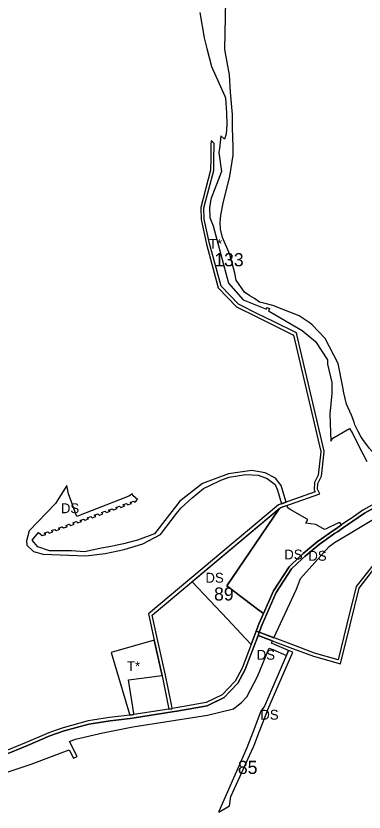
# Model space of a CAD drawing. Extents: x -477304 to -465641, y -1159113 to -1149285.
# Drawn here: x -470101 to -469785, y -1153834 to -1153108 of the extents above; entities that cross this region are included whole.
import ezdxf

# ---------------------------------------------------------------- set-up
doc = ezdxf.new("R2010")
doc.units = 0
for name, color, linetype in [('14', 7, 'Continuous'), ('17', 7, 'Continuous'), ('35', 7, 'Continuous'), ('4', 7, 'Continuous'), ('60', 7, 'Continuous')]:
    doc.layers.add(name, color=color, linetype=linetype)

msp = doc.modelspace()

# ---------------------------------------------------------------- linework, layer by layer
at = {"layer": '14'}
for p, q in [((-469861.91, -1153557.27), (-469941.15, -1153623.82)), ((-469941.15, -1153623.82), (-469908.95, -1153658.04)), ((-469885.46, -1153645.71), (-469895.39, -1153638.21)), ((-469881.57, -1153648.65), (-469885.46, -1153645.71)), ((-469876.12, -1153652.76), (-469881.57, -1153648.65)), ((-469908.95, -1153658.04), (-469892.51, -1153675.5)), ((-469887.31, -1153681.03), (-469882.68, -1153668.8)), ((-469892.51, -1153675.5), (-469887.31, -1153681.03)), ((-469853.16, -1153686.42), (-469875.1, -1153737.35)), ((-469849.49, -1153688.02), (-469853.16, -1153686.42)), ((-469875.1, -1153737.35), (-469878.47, -1153741.63)), ((-469878.47, -1153741.63), (-469885.5, -1153760.21)), ((-469879.65, -1153759.93), (-469872.26, -1153740.43)), ((-469888.77, -1153782.27), (-469885.17, -1153774.35)), ((-469897.31, -1153801.05), (-469888.77, -1153782.27)), ((-469899.91, -1153795.18), (-469916.58, -1153833.33)), ((-469905.73, -1153819.57), (-469897.31, -1153801.05)), ((-469907.11, -1153828.02), (-469905.73, -1153819.57)), ((-469916.76, -1153833.74), (-469907.11, -1153828.02)), ((-469916.58, -1153833.33), (-469916.76, -1153833.74))]:
    msp.add_line(p, q, dxfattribs=at)
for points in [[(-469895.39, -1153638.21), (-469909.36, -1153627.65), (-469861.91, -1153557.27)], [(-469882.68, -1153668.8), (-469879.93, -1153661.52), (-469876.12, -1153652.76)], [(-469872.26, -1153740.43), (-469872.18, -1153740.2), (-469849.49, -1153688.02)], [(-469885.5, -1153760.21), (-469891.17, -1153775.19), (-469899.91, -1153795.18)], [(-469885.17, -1153774.35), (-469884.84, -1153773.63), (-469879.65, -1153759.93)]]:
    msp.add_lwpolyline(points, dxfattribs=at)
at = {"layer": '17'}
for p, q in [((-469975.46, -1153677.14), (-470014.7, -1153688.4)), ((-469968.4, -1153709.21), (-469975.46, -1153677.14)), ((-470014.7, -1153688.4), (-469998.01, -1153744.48)), ((-469998.82, -1153713.09), (-469968.4, -1153709.21)), ((-469994.18, -1153743.75), (-469998.82, -1153713.09)), ((-469998.01, -1153744.48), (-469997.87, -1153745.36)), ((-469997.87, -1153745.36), (-469994.02, -1153744.79)), ((-469994.02, -1153744.79), (-469994.18, -1153743.75))]:
    msp.add_line(p, q, dxfattribs=at)
at = {"layer": '35'}
for p, q in [((-469934.01, -1153105.13), (-469930.18, -1153128.18)), ((-469930.18, -1153128.18), (-469927.69, -1153137.79)), ((-469927.69, -1153137.79), (-469923.48, -1153154.05)), ((-469923.48, -1153154.05), (-469911.32, -1153181.38)), ((-469911.32, -1153181.38), (-469910.63, -1153182.94)), ((-469910.63, -1153182.94), (-469909.76, -1153196.47)), ((-469909.76, -1153196.47), (-469909.59, -1153207.08)), ((-469909.59, -1153207.08), (-469909.92, -1153215.75)), ((-469909.92, -1153215.75), (-469910.65, -1153217.65)), ((-469903.69, -1153227.03), (-469904.29, -1153210.3)), ((-469914.79, -1153217.53), (-469916.18, -1153229.08)), ((-469911.46, -1153220.44), (-469914.79, -1153217.53)), ((-469916.18, -1153229.08), (-469916.62, -1153232.73)), ((-469903.7, -1153232.71), (-469903.69, -1153227.03)), ((-469903.79, -1153235.09), (-469903.7, -1153232.71)), ((-469915.62, -1153296.43), (-469914.87, -1153289.68)), ((-469915.06, -1153302.48), (-469915.62, -1153296.43)), ((-469921.92, -1153299.34), (-469907.91, -1153351.56)), ((-469913.29, -1153310.07), (-469915.06, -1153302.48)), ((-469907.91, -1153351.56), (-469894.62, -1153366.93)), ((-469884.19, -1153365.79), (-469888.57, -1153363.17)), ((-469879.81, -1153368.87), (-469884.19, -1153365.79)), ((-469875.85, -1153369.85), (-469879.81, -1153368.87)), ((-469872.98, -1153373.93), (-469870.68, -1153374.87)), ((-469870.68, -1153374.87), (-469871.54, -1153376.88)), ((-469833.46, -1153388.17), (-469843.6, -1153381.6)), ((-469831.79, -1153389.68), (-469833.46, -1153388.17)), ((-469819.99, -1153402.16), (-469831.79, -1153389.68)), ((-469817.76, -1153421.41), (-469817.94, -1153425.43)), ((-469817.94, -1153425.43), (-469813.92, -1153442.22)), ((-469813.92, -1153442.22), (-469813.78, -1153452.18)), ((-469796.05, -1153472.06), (-469800.64, -1153461.93)), ((-469793.44, -1153478.47), (-469796.05, -1153472.06)), ((-469792.99, -1153480.68), (-469793.44, -1153478.47)), ((-469789.85, -1153486.93), (-469792.99, -1153480.68)), ((-469787.54, -1153491.35), (-469789.85, -1153486.93)), ((-469785.57, -1153494.24), (-469787.54, -1153491.35)), ((-469814.76, -1153495.63), (-469812.93, -1153492.98)), ((-469789.27, -1153500.37), (-469781.93, -1153514.31)), ((-469892.13, -1153526.17), (-469880.96, -1153526.58)), ((-470055.02, -1153536.1), (-470065.3, -1153552.42)), ((-470053.46, -1153543.75), (-470055.02, -1153536.1)), ((-469931.48, -1153534.12), (-469952.3, -1153550.45)), ((-469925.02, -1153536.07), (-469915.04, -1153531.24)), ((-469859.91, -1153535.97), (-469865.11, -1153529.32)), ((-470050.53, -1153551.96), (-470053.46, -1153543.75)), ((-469990.92, -1153548.94), (-469994.76, -1153545.62)), ((-469951.31, -1153556.6), (-469940.9, -1153547.21)), ((-470065.3, -1153552.42), (-470089.45, -1153577.34)), ((-470048.31, -1153558.05), (-470050.53, -1153551.96)), ((-470010.53, -1153556.09), (-470007.27, -1153554.92)), ((-470009.21, -1153557.2), (-470010.53, -1153556.09)), ((-469996.18, -1153552.52), (-469997.5, -1153551.43)), ((-469955.18, -1153561.55), (-469951.31, -1153556.6)), ((-469860.9, -1153556.42), (-469861.91, -1153557.27)), ((-469854.62, -1153554.21), (-469860.9, -1153556.42)), ((-469859.56, -1153552.77), (-469855.45, -1153551.32)), ((-469853.93, -1153556.57), (-469854.62, -1153554.21)), ((-469851.67, -1153557.88), (-469853.93, -1153556.57)), ((-469836.17, -1153566.88), (-469851.67, -1153557.88)), ((-470046.08, -1153564.42), (-470048.31, -1153558.05)), ((-470033.34, -1153564.33), (-470032.01, -1153565.41)), ((-470030.11, -1153563.14), (-470026.82, -1153561.98)), ((-470026.82, -1153561.98), (-470025.48, -1153563.09)), ((-469969.79, -1153580.6), (-469955.18, -1153561.55)), ((-470051.56, -1153572.43), (-470048.28, -1153571.25)), ((-470045.03, -1153570.11), (-470041.76, -1153568.94)), ((-469804.99, -1153571.96), (-469806.61, -1153569.92)), ((-470089.45, -1153577.34), (-470091.71, -1153586.53)), ((-470072.38, -1153578.4), (-470071.08, -1153579.47)), ((-470054.82, -1153573.62), (-470056.14, -1153572.54)), ((-469819.05, -1153575.7), (-469820.5, -1153576.22)), ((-470091.71, -1153586.53), (-470091.43, -1153590.56)), ((-469990.88, -1153585.8), (-470003.56, -1153589.31)), ((-469986, -1153589.39), (-469969.79, -1153580.6)), ((-469811.4, -1153588.14), (-469804.73, -1153584.11)), ((-470025.19, -1153593.64), (-470038.9, -1153596.57)), ((-470003.06, -1153594.4), (-469986, -1153589.39)), ((-469845.92, -1153630.44), (-469842.45, -1153620.83)), ((-469866.58, -1153674.9), (-469845.92, -1153630.44)), ((-469895.39, -1153638.21), (-469885.46, -1153645.71)), ((-469885.46, -1153645.71), (-469881.57, -1153648.65)), ((-469881.57, -1153648.65), (-469876.12, -1153652.76)), ((-469880.94, -1153672.67), (-469890.22, -1153697.21)), ((-469880.13, -1153672.98), (-469880.94, -1153672.67)), ((-469871.3, -1153676.32), (-469880.13, -1153672.98)), ((-469879.88, -1153669.86), (-469866.58, -1153674.9)), ((-469867.85, -1153677.63), (-469871.3, -1153676.32)), ((-469868.8, -1153679.68), (-469867.85, -1153677.63)), ((-469865.9, -1153680.93), (-469868.8, -1153679.68)), ((-469853.16, -1153686.42), (-469865.9, -1153680.93)), ((-469881.47, -1153710.08), (-469871.25, -1153684.94)), ((-469871.25, -1153684.94), (-469870.91, -1153684.21)), ((-469870.91, -1153684.21), (-469867.51, -1153685.68)), ((-469867.51, -1153685.68), (-469855.14, -1153691.01)), ((-469855.14, -1153691.01), (-469853.16, -1153686.42)), ((-469892.8, -1153703.93), (-469899.47, -1153716.14)), ((-469891.26, -1153728.85), (-469881.47, -1153710.08)), ((-469896.16, -1153733.92), (-469891.26, -1153728.85)), ((-469903.47, -1153739.49), (-469896.16, -1153733.92)), ((-469995.09, -1153756.04), (-469927.03, -1153745.53)), ((-469927.03, -1153745.53), (-469903.47, -1153739.49)), ((-470010.4, -1153749.91), (-470015.72, -1153750.56)), ((-470022.46, -1153761.65), (-469995.09, -1153756.04)), ((-470045.67, -1153783.06), (-470052.8, -1153769.37)), ((-470087.67, -1153789.98), (-470052.84, -1153777.05)), ((-470052.84, -1153777.05), (-470048.96, -1153784.66)), ((-470048.96, -1153784.66), (-470045.67, -1153783.06))]:
    msp.add_line(p, q, dxfattribs=at)
for points in [[(-469906.22, -1153177.73), (-469906.93, -1153161.67), (-469911.29, -1153138.57), (-469910.39, -1153094.13), (-469908.46, -1153082.97)], [(-469904.29, -1153210.3), (-469904.3, -1153198.04), (-469906.22, -1153177.73)], [(-469910.65, -1153217.65), (-469911.03, -1153218.63), (-469911.46, -1153220.44)], [(-469916.62, -1153232.73), (-469914.2, -1153249.76), (-469924.01, -1153275.25), (-469925.36, -1153283.09)], [(-469914.87, -1153289.68), (-469912.78, -1153278.79), (-469906.72, -1153254.26), (-469903.79, -1153235.09)], [(-469925.36, -1153283.09), (-469925.04, -1153291.71), (-469921.92, -1153299.34)], [(-469902.03, -1153342.48), (-469906.82, -1153325.51), (-469913.29, -1153310.07)], [(-469888.57, -1153363.17), (-469893.22, -1153359.8), (-469901.02, -1153348.86), (-469902.03, -1153342.48)], [(-469894.62, -1153366.93), (-469873.41, -1153375.37), (-469872.98, -1153373.93)], [(-469843.6, -1153381.6), (-469867.5, -1153371.92), (-469875.85, -1153369.85)], [(-469871.54, -1153376.88), (-469840.78, -1153394.87), (-469828.75, -1153404.82), (-469817.76, -1153421.41)], [(-469800.64, -1153461.93), (-469802.91, -1153451.78), (-469803.75, -1153446.4), (-469808.11, -1153424.97), (-469819.99, -1153402.16)], [(-469813.78, -1153452.18), (-469815.68, -1153471.08), (-469814.76, -1153495.63)], [(-469812.93, -1153492.98), (-469797.79, -1153484), (-469794.61, -1153488.97), (-469789.27, -1153500.37)], [(-469767.37, -1153516.16), (-469779.49, -1153502.3), (-469785.57, -1153494.24)], [(-469886.83, -1153522.42), (-469907.93, -1153525.41), (-469931.48, -1153534.12)], [(-469915.04, -1153531.24), (-469907.46, -1153528.64), (-469892.13, -1153526.17)], [(-469865.11, -1153529.32), (-469874.62, -1153524.63), (-469886.83, -1153522.42)], [(-469880.96, -1153526.58), (-469872.71, -1153529.74), (-469865.31, -1153535.05)], [(-469940.9, -1153547.21), (-469930.65, -1153538.75), (-469925.02, -1153536.07)], [(-469742.44, -1153534.42), (-469748.64, -1153538.33), (-469759.24, -1153544.99), (-469775.93, -1153556.66), (-469783.97, -1153561.24), (-469794.67, -1153568.52), (-469797.47, -1153570.42), (-469803.29, -1153574.43), (-469808.8, -1153578.22), (-469811.32, -1153579.97), (-469825.44, -1153589.77), (-469838.04, -1153600.39), (-469840.84, -1153603), (-469850.52, -1153612.05), (-469864.45, -1153633.46), (-469877.15, -1153662.65), (-469879.88, -1153669.86)], [(-469865.31, -1153535.05), (-469863.27, -1153540.38), (-469859.56, -1153552.77)], [(-469855.45, -1153551.32), (-469857.51, -1153544.24), (-469859.91, -1153535.97)], [(-469994.76, -1153545.62), (-469994.94, -1153545.05), (-469995.4, -1153543.59), (-469998.51, -1153545.86), (-470046.08, -1153564.42)], [(-469997.5, -1153551.43), (-469994.24, -1153550.26), (-469992.93, -1153551.35), (-469990.92, -1153548.94)], [(-469952.3, -1153550.45), (-469975.42, -1153580.01), (-469990.88, -1153585.8)], [(-470025.48, -1153563.09), (-470022.23, -1153561.89), (-470023.57, -1153560.81), (-470020.29, -1153559.62), (-470018.95, -1153560.73), (-470015.71, -1153559.54), (-470017.03, -1153558.46), (-470013.77, -1153557.28), (-470012.46, -1153558.36), (-470009.21, -1153557.2)], [(-470007.27, -1153554.92), (-470005.94, -1153556.02), (-470002.68, -1153554.84), (-470004.03, -1153553.78), (-470000.78, -1153552.59)], [(-470000.78, -1153552.59), (-469999.44, -1153553.69), (-469996.18, -1153552.52)], [(-469861.91, -1153557.27), (-469909.36, -1153627.65), (-469895.39, -1153638.21)], [(-469804.73, -1153584.11), (-469757.7, -1153555.8), (-469754.88, -1153554.18)], [(-470035.27, -1153566.59), (-470036.6, -1153565.51), (-470033.34, -1153564.33)], [(-470032.01, -1153565.41), (-470028.75, -1153564.24), (-470030.11, -1153563.14)], [(-470056.14, -1153572.54), (-470052.89, -1153571.38), (-470051.56, -1153572.43)], [(-470048.28, -1153571.25), (-470049.61, -1153570.18), (-470046.36, -1153569.02), (-470045.03, -1153570.11)], [(-470041.76, -1153568.94), (-470043.1, -1153567.85), (-470039.85, -1153566.67), (-470038.51, -1153567.78), (-470035.27, -1153566.59)], [(-469876.12, -1153652.76), (-469867.1, -1153632.03), (-469852.84, -1153610.11), (-469842.89, -1153600.81), (-469840.03, -1153598.14), (-469827.27, -1153587.39), (-469813.03, -1153577.5), (-469810.5, -1153575.75), (-469804.99, -1153571.96)], [(-469837.53, -1153570.41), (-469835.68, -1153567.16), (-469836.17, -1153566.88)], [(-469820.5, -1153576.22), (-469828.45, -1153571.77), (-469837.53, -1153570.41)], [(-469806.61, -1153569.92), (-469807.8, -1153570.22), (-469819.05, -1153575.7)], [(-470081.4, -1153591.94), (-470086.72, -1153586.05), (-470080.94, -1153578.88)], [(-470080.94, -1153578.88), (-470077.58, -1153581.78), (-470074.33, -1153580.61)], [(-470074.33, -1153580.61), (-470075.66, -1153579.52), (-470072.38, -1153578.4)], [(-470071.08, -1153579.47), (-470067.85, -1153578.29), (-470069.14, -1153577.23)], [(-470069.14, -1153577.23), (-470065.93, -1153576.09), (-470064.61, -1153577.14)], [(-470064.61, -1153577.14), (-470061.35, -1153575.96), (-470062.66, -1153574.88)], [(-470062.66, -1153574.88), (-470059.4, -1153573.72), (-470058.06, -1153574.79), (-470054.82, -1153573.62)], [(-470091.43, -1153590.56), (-470085.53, -1153596.32), (-470076.56, -1153598.65), (-470037.86, -1153600.25)], [(-470038.9, -1153596.57), (-470050.73, -1153595.63), (-470070.76, -1153595.65), (-470081.4, -1153591.94)], [(-470003.56, -1153589.31), (-470013.44, -1153591.49), (-470025.19, -1153593.64)], [(-469842.45, -1153620.83), (-469816.2, -1153591.55), (-469811.4, -1153588.14)], [(-470037.86, -1153600.25), (-470020.14, -1153598.04), (-470003.06, -1153594.4)], [(-469890.22, -1153697.21), (-469892.68, -1153703.71), (-469892.8, -1153703.93)], [(-469899.47, -1153716.14), (-469906.07, -1153723.14), (-469911.9, -1153729.32), (-469923.8, -1153735.08)], [(-469923.8, -1153735.08), (-469927.41, -1153736.82), (-469955.04, -1153741.64), (-469959.11, -1153742.5), (-469993.57, -1153747.76), (-469997.47, -1153748.33), (-470010.4, -1153749.91)], [(-470015.72, -1153750.56), (-470031.12, -1153752.97), (-470035.04, -1153753.64), (-470057.45, -1153759.75), (-470070.47, -1153764.33), (-470091.01, -1153773.14), (-470108.03, -1153780.1), (-470115.74, -1153783.08), (-470129.3, -1153787.64), (-470140.23, -1153791.32), (-470144.94, -1153792.24)], [(-470052.8, -1153769.37), (-470047.33, -1153767.42), (-470022.46, -1153761.65)], [(-470178.15, -1153813.17), (-470133.39, -1153805.3), (-470087.67, -1153789.98)]]:
    msp.add_lwpolyline(points, dxfattribs=at)
at = {"layer": '4'}
for p, q in [((-469923.67, -1153221.89), (-469924.03, -1153225.48)), ((-469776.88, -1153609.23), (-469791.81, -1153628.18)), ((-469791.81, -1153628.18), (-469800.13, -1153662.51)), ((-469797.21, -1153663.22), (-469789.05, -1153629.52)), ((-469800.13, -1153662.51), (-469808.01, -1153695.03)), ((-469879.88, -1153669.86), (-469882.68, -1153668.8)), ((-469882.68, -1153668.8), (-469879.88, -1153669.86)), ((-469880.94, -1153672.67), (-469879.88, -1153669.86)), ((-469879.88, -1153669.86), (-469880.94, -1153672.67)), ((-469850.88, -1153680.84), (-469879.88, -1153669.86)), ((-469829.53, -1153688.92), (-469850.88, -1153680.84)), ((-469808.01, -1153695.03), (-469829.53, -1153688.92)), ((-470069.83, -1153760.86), (-470071.56, -1153761.53)), ((-470063.02, -1153758.53), (-470069.83, -1153760.86))]:
    msp.add_line(p, q, dxfattribs=at)
for points in [[(-469920.92, -1153224.53), (-469922.25, -1153223.26), (-469923.67, -1153221.89)], [(-469924.03, -1153225.48), (-469924.14, -1153237.9), (-469924.24, -1153248.64), (-469933.25, -1153282.8), (-469932.94, -1153293.65), (-469928.03, -1153316.16), (-469917.44, -1153355.79), (-469900.76, -1153373.26), (-469882.11, -1153382.51), (-469868.23, -1153389.4), (-469848.65, -1153399.12), (-469823.97, -1153505.24), (-469823.97, -1153505.33), (-469826.25, -1153526.64), (-469829.73, -1153533.5), (-469829.85, -1153539.94), (-469828.88, -1153541.96), (-469862.41, -1153553.77), (-469980.74, -1153653.15), (-469975.5, -1153676.95), (-469968.34, -1153709.45), (-469962.14, -1153739.93)], [(-469959.17, -1153739.45), (-469959.96, -1153735.58), (-469965.41, -1153708.83), (-469972.57, -1153676.31), (-469977.42, -1153654.27), (-469860.9, -1153556.42), (-469825.83, -1153544.07), (-469824.72, -1153543.68), (-469826.84, -1153539.28), (-469826.74, -1153534.24), (-469823.33, -1153527.51), (-469820.97, -1153505.51), (-469820.96, -1153504.92), (-469845.73, -1153398.41), (-469846.04, -1153397.06), (-469866.9, -1153386.71), (-469880.78, -1153379.82), (-469898.95, -1153370.81), (-469914.74, -1153354.27), (-469925.11, -1153315.45), (-469929.95, -1153293.28), (-469930.24, -1153283.15), (-469921.24, -1153249.04), (-469921.14, -1153237.93), (-469921.03, -1153225.64), (-469920.92, -1153224.53)], [(-469879.88, -1153669.86), (-469877.15, -1153662.65), (-469864.45, -1153633.46), (-469850.52, -1153612.05), (-469840.84, -1153603), (-469838.04, -1153600.39), (-469825.44, -1153589.77), (-469811.32, -1153579.97), (-469808.8, -1153578.22), (-469803.29, -1153574.43), (-469797.47, -1153570.42), (-469794.67, -1153568.52), (-469783.97, -1153561.24), (-469775.93, -1153556.66), (-469759.24, -1153544.99), (-469748.64, -1153538.33), (-469742.44, -1153534.42)], [(-469777.54, -1153554.12), (-469785.56, -1153558.69), (-469796.36, -1153566.04), (-469799.16, -1153567.94), (-469804.99, -1153571.96), (-469810.5, -1153575.75), (-469813.03, -1153577.5), (-469827.27, -1153587.39), (-469840.03, -1153598.14), (-469842.89, -1153600.81), (-469852.84, -1153610.11), (-469867.1, -1153632.03), (-469876.12, -1153652.76), (-469879.93, -1153661.52), (-469882.68, -1153668.8)], [(-469789.05, -1153629.52), (-469774.56, -1153611.14), (-469755.23, -1153588.67)], [(-469880.94, -1153672.67), (-469851.94, -1153683.65), (-469830.47, -1153691.77), (-469805.82, -1153698.77), (-469797.21, -1153663.22)], [(-470144.94, -1153792.24), (-470140.23, -1153791.32), (-470129.3, -1153787.64), (-470115.74, -1153783.08), (-470108.03, -1153780.1), (-470091.01, -1153773.14), (-470070.47, -1153764.33), (-470057.45, -1153759.75), (-470035.04, -1153753.64), (-470031.12, -1153752.97), (-470015.72, -1153750.56), (-469997.47, -1153748.33), (-469993.57, -1153747.76), (-469959.11, -1153742.5), (-469955.04, -1153741.64), (-469927.41, -1153736.82), (-469911.9, -1153729.32), (-469906.07, -1153723.14), (-469899.47, -1153716.14), (-469892.68, -1153703.71), (-469880.94, -1153672.67)], [(-469882.68, -1153668.8), (-469887.31, -1153681.03), (-469895.41, -1153702.45), (-469901.92, -1153714.36), (-469908.25, -1153721.08), (-469913.7, -1153726.86), (-469928.34, -1153733.94), (-469955.61, -1153738.69), (-469959.17, -1153739.45)], [(-469962.14, -1153739.93), (-469994.02, -1153744.79), (-469997.87, -1153745.36), (-470016.13, -1153747.59), (-470031.6, -1153750.01), (-470035.69, -1153750.71), (-470058.34, -1153756.88), (-470063.02, -1153758.53)], [(-469962.14, -1153739.93), (-469959.65, -1153739.55), (-469959.17, -1153739.45)], [(-469959.17, -1153739.45), (-469959.65, -1153739.55), (-469962.14, -1153739.93)], [(-470071.56, -1153761.53), (-470092.17, -1153770.37), (-470109.14, -1153777.31), (-470116.76, -1153780.26), (-470130.26, -1153784.8), (-470141, -1153788.41), (-470145.52, -1153789.3)]]:
    msp.add_lwpolyline(points, dxfattribs=at)

# ---------------------------------------------------------------- texts
at = {"layer": '14'}
for p in [(-469928.94, -1153624.66), (-469879, -1153749.51)]:
    msp.add_text('DS', height=9, dxfattribs=at).set_placement(p)
at = {"layer": '17'}
msp.add_text('T*', height=9, dxfattribs=at).set_placement((-470000.39, -1153705.28))
at = {"layer": '35'}
for p in [(-470060.55, -1153561.33), (-469857.17, -1153603.49), (-469835.28, -1153604.66), (-469882.31, -1153694.87)]:
    msp.add_text('DS', height=9, dxfattribs=at).set_placement(p)
at = {"layer": '4'}
msp.add_text('T*', height=9, dxfattribs=at).set_placement((-469925.69, -1153320.28))
at = {"layer": '60'}
for s, p in [('133', (-469920.91, -1153336.32)), ('89', (-469921.08, -1153640.95)), ('85', (-469899.4, -1153799))]:
    msp.add_text(s, height=12, dxfattribs=at).set_placement(p)

doc.saveas('drawing.dxf')
